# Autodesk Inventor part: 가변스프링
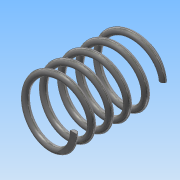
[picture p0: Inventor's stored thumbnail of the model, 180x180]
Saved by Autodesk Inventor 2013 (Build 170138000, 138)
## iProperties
Created: 2017-12
Part Number: 가변스프링
Material: 스테인리스강
Document SubType Name: Modeling
Designer: Administrator
Mass: 7.08194 g
Surface Area: 17.761 cm^2
Volume: 0.876478 cm^3
Density: 8.08 g/cm^3
Author: Administrator
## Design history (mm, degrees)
sketch "스케치1"
  geometry: L1 (0, 0)-(9, 0); L2 (9, 0)-(9, 28.5); L3 (9, 28.5)-(0, 28.5); L4 (0, 28.5)-(0, 0); C1 r 1 at (9, 0)
  constraints: 8 end point, 2 parallel, 1 centre point, 1 coincident, 1 horizontal, 1 perpendicular
  dimensions: "d0" = 28.5 distance of L3.end L1.start (derived); "d1" = 18 diameter of L2 L4; "d2" = 2 diameter of C1
feature "코일1" sketch "스케치1" pitch "d3" = 10; turns "d5" = 5; dims "d4" = 28.5 (= d0), "d6" = 0, angle "d7" = 90 deg, angle "d8" = 90 deg, "d9" = 0, "d10" = 0
sketch "스케치2"
  geometry: L1 (28.5, 15)-(0, 15); L2 (0, 15)-(0, -15); L3 (0, -15)-(28.5, -15); L4 (28.5, -15)-(28.5, 15); 4 further points
  constraints: 8 end point, 4 coincident, 2 midpoint, 2 parallel, 1 horizontal, 1 perpendicular
  dimensions: "d11" = 30 distance of L3.end L1.start
extrude "돌출1" sketch "스케치2" stored distance "d13" = 0; taper "d14" = 0 deg
node "솔리드1"
